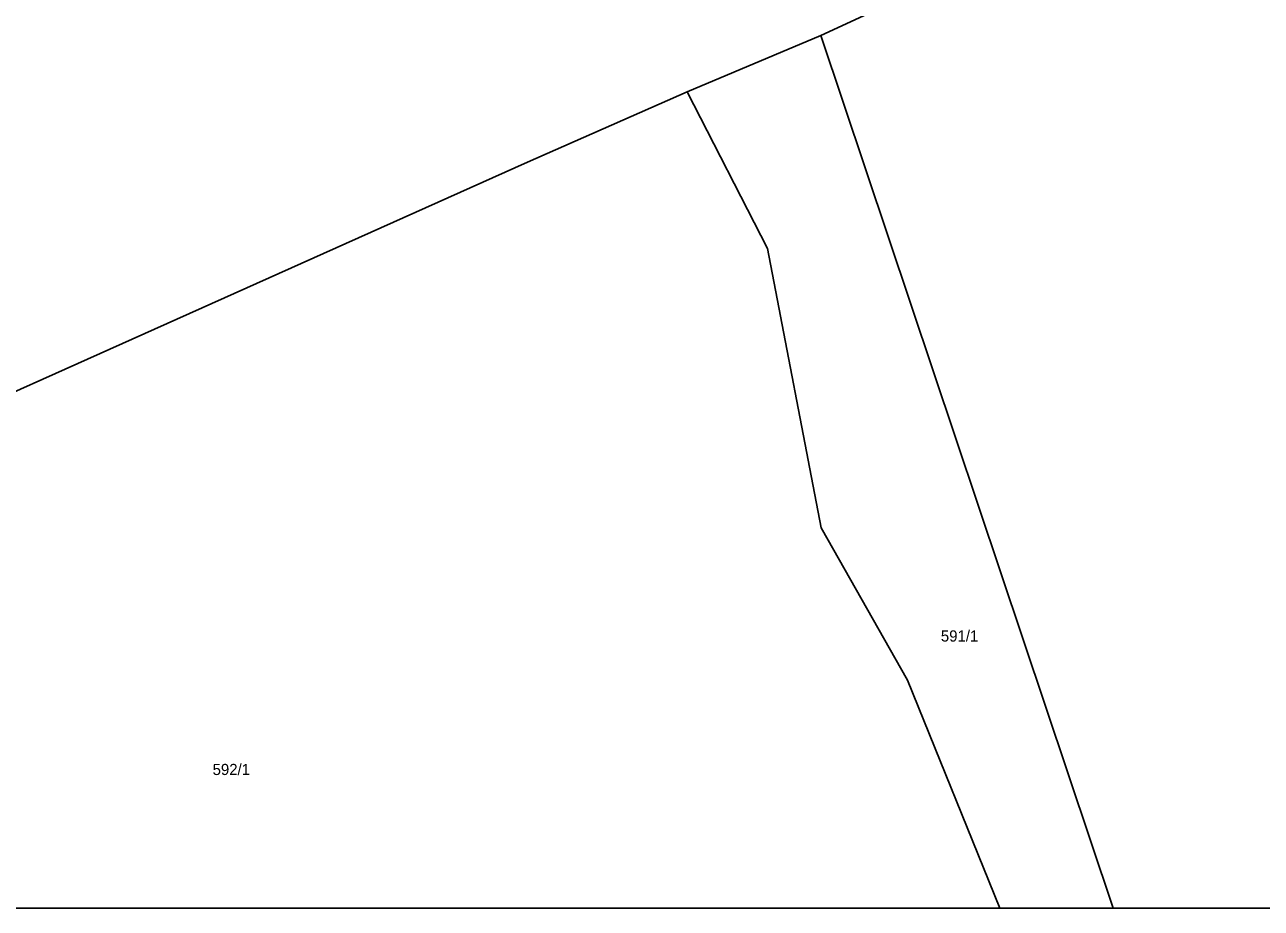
# Model space of a CAD drawing. Extents: x -873642 to -872917, y -1012962 to -1012567.
# Drawn here: x -873378.9 to -873284.9, y -1012961.7 to -1012894.5 of the extents above; entities that cross this region are included whole.
import ezdxf

# ---------------------------------------------------------------- set-up
doc = ezdxf.new("R2010")
doc.units = 0
doc.layers.add('cisla_parcelni_kn', color=7, linetype='Continuous')
doc.layers.add('parcely_kn', color=7, linetype='Continuous')

msp = doc.modelspace()

# ---------------------------------------------------------------- linework, layer by layer
at = {"layer": 'parcely_kn'}
for p, q in [((-873415.745, -1012961.688), (-873304.734, -1012961.688)), ((-873415.745, -1012961.688), (-873304.734, -1012961.688)), ((-873304.734, -1012961.688), (-873296.12, -1012961.688)), ((-873304.734, -1012961.688), (-873296.12, -1012961.688)), ((-873296.12, -1012961.688), (-873219.616, -1012961.688)), ((-873296.12, -1012961.688), (-873219.616, -1012961.688))]:
    msp.add_line(p, q, dxfattribs=at)
for points in [[(-873149.77, -1012848.73), (-873202.95, -1012863.9), (-873307.96, -1012890.45), (-873318.36, -1012895.27), (-873328.54, -1012899.56), (-873340.69, -1012904.93), (-873416.15, -1012938.7), (-873417.98, -1012939.52), (-873435.72, -1012947.37), (-873445.76, -1012897.62), (-873478.14, -1012904.47), (-873481.91, -1012884.93)], [(-873149.77, -1012848.73), (-873202.95, -1012863.9), (-873307.96, -1012890.45), (-873318.36, -1012895.27), (-873328.54, -1012899.56), (-873340.69, -1012904.93), (-873416.15, -1012938.7), (-873417.98, -1012939.52), (-873435.72, -1012947.37), (-873445.76, -1012897.62), (-873478.14, -1012904.47), (-873481.91, -1012884.93)], [(-873219.616, -1012961.688), (-873165.87, -1012937.08), (-873157.54, -1012937.35), (-873150.44, -1012877.16), (-873149.77, -1012848.73), (-873202.95, -1012863.9), (-873307.96, -1012890.45), (-873318.36, -1012895.27), (-873296.12, -1012961.688)], [(-873219.616, -1012961.688), (-873165.87, -1012937.08), (-873157.54, -1012937.35), (-873150.44, -1012877.16), (-873149.77, -1012848.73), (-873202.95, -1012863.9), (-873307.96, -1012890.45), (-873318.36, -1012895.27), (-873296.12, -1012961.688)], [(-873296.12, -1012961.688), (-873318.36, -1012895.27), (-873328.54, -1012899.56), (-873322.43, -1012911.49), (-873318.35, -1012932.75), (-873311.77, -1012944.32), (-873304.734, -1012961.688)], [(-873296.12, -1012961.688), (-873318.36, -1012895.27), (-873328.54, -1012899.56), (-873322.43, -1012911.49), (-873318.35, -1012932.75), (-873311.77, -1012944.32), (-873304.734, -1012961.688)], [(-873304.734, -1012961.688), (-873311.77, -1012944.32), (-873318.35, -1012932.75), (-873322.43, -1012911.49), (-873328.54, -1012899.56), (-873340.69, -1012904.93), (-873416.15, -1012938.7), (-873417.98, -1012939.52), (-873415.745, -1012961.688)], [(-873304.734, -1012961.688), (-873311.77, -1012944.32), (-873318.35, -1012932.75), (-873322.43, -1012911.49), (-873328.54, -1012899.56), (-873340.69, -1012904.93), (-873416.15, -1012938.7), (-873417.98, -1012939.52), (-873415.745, -1012961.688)]]:
    msp.add_lwpolyline(points, dxfattribs=at)

# ---------------------------------------------------------------- texts
at = {"layer": 'cisla_parcelni_kn'}
for s, p in [('591/1', (-873309.233, -1012941.394)), ('591/1', (-873309.233, -1012941.394)), ('592/1', (-873364.64, -1012951.55)), ('592/1', (-873364.64, -1012951.55))]:
    msp.add_text(s, height=0.85, dxfattribs=at).set_placement(p)

doc.saveas('drawing.dxf')
